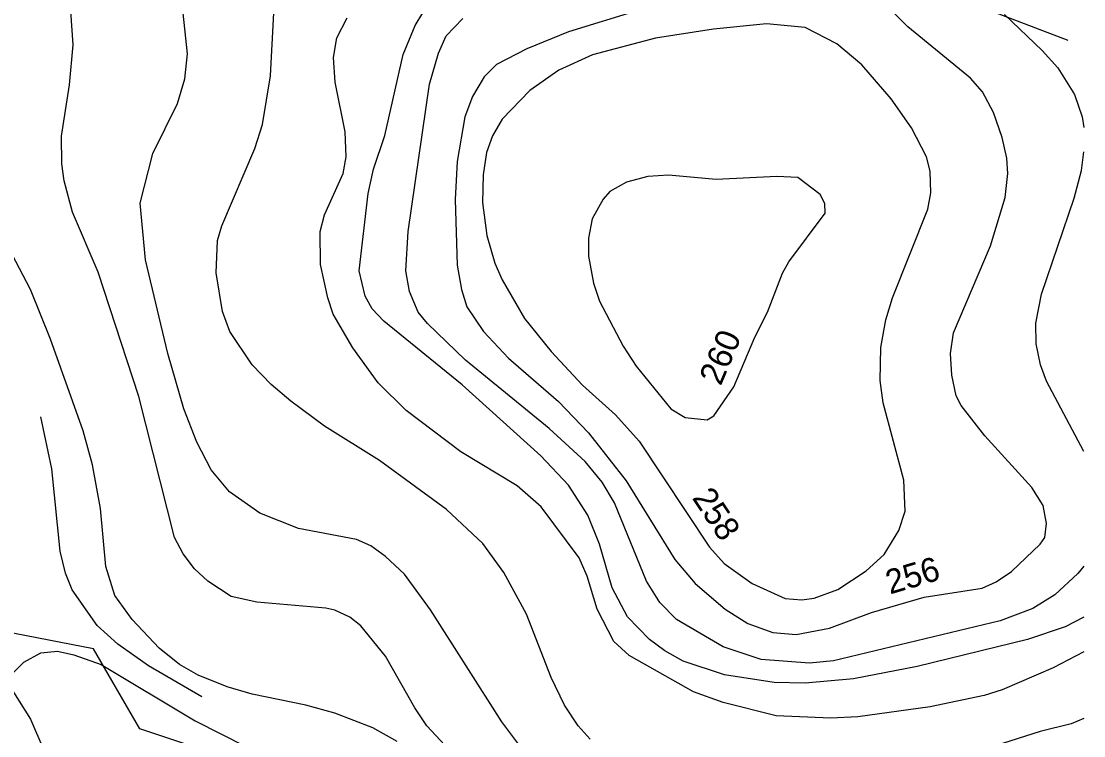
# Model space of a CAD drawing. Extents: x -662500 to -655523, y -1056000 to -1049993.
# Drawn here: x -659235.8 to -658797.7, y -1052866.9 to -1052572.3 of the extents above; entities that cross this region are included whole.
import ezdxf

# ---------------------------------------------------------------- set-up
doc = ezdxf.new("R2010")
doc.units = 0
doc.layers.add('Vrstva 24', color=7, linetype='Continuous')
doc.layers.add('Vrstva 7', color=7, linetype='Continuous')

msp = doc.modelspace()

# ---------------------------------------------------------------- linework, layer by layer
at = {"layer": 'Vrstva 24'}
for points in [[(-658804.21, -1052580.31), (-658897.5, -1052544.5), (-658920, -1052554.5), (-658965.5, -1052545)], [(-659139, -1052880), (-659187, -1052864), (-659206, -1052831), (-659248, -1052823), (-659254.5, -1052824.5), (-659232, -1052860), (-659216, -1052897.5)]]:
    msp.add_lwpolyline(points, dxfattribs=at)
at = {"layer": 'Vrstva 7'}
for p, q in [((-659167.29, -1052585.76), (-659170.28, -1052557.57)), ((-658870.28, -1052574.66), (-658888.08, -1052556.72)), ((-659214.41, -1052582.06), (-659215.41, -1052568.11)), ((-658980.62, -1052567.54), (-659010.24, -1052576.65)), ((-659133.11, -1052594.88), (-659131.69, -1052568.82)), ((-659105.78, -1052579.21), (-659101.51, -1052570.96)), ((-659073.46, -1052574.09), (-659070.32, -1052568.82)), ((-659060.64, -1052578.36), (-659053.81, -1052571.24)), ((-658830.41, -1052569.53), (-658814.89, -1052584.34)), ((-659078.3, -1052586.05), (-659073.46, -1052574.09)), ((-659010.24, -1052576.65), (-659027.33, -1052583.63)), ((-658950.44, -1052575.51), (-658974.36, -1052579.35)), ((-658928.51, -1052573.38), (-658950.44, -1052575.51)), ((-658912.57, -1052574.94), (-658928.51, -1052573.38)), ((-658899.61, -1052581.63), (-658912.57, -1052574.94)), ((-658844.37, -1052595.73), (-658870.28, -1052574.66)), ((-659107.06, -1052587.19), (-659105.78, -1052579.21)), ((-659063.77, -1052585.48), (-659060.64, -1052578.36)), ((-658974.36, -1052579.35), (-659000.27, -1052586.19)), ((-659215.98, -1052598.58), (-659214.41, -1052582.06)), ((-659168.42, -1052596.01), (-659167.29, -1052585.76)), ((-659067.48, -1052598.29), (-659063.77, -1052585.48)), ((-659027.33, -1052583.63), (-659039.85, -1052590.18)), ((-658889.21, -1052590.32), (-658899.61, -1052581.63)), ((-658814.89, -1052584.34), (-658808.49, -1052591.46)), ((-659106.35, -1052597.44), (-659107.06, -1052587.19)), ((-659085.98, -1052619.36), (-659078.3, -1052586.05)), ((-659039.85, -1052590.18), (-659044.98, -1052595.16)), ((-659000.27, -1052586.19), (-659014.23, -1052592.46)), ((-659014.23, -1052592.46), (-659026.19, -1052600.85)), ((-658877.11, -1052604.27), (-658889.21, -1052590.32)), ((-658808.49, -1052591.46), (-658801.51, -1052602.56)), ((-659219.25, -1052619.65), (-659215.98, -1052598.58)), ((-659171.41, -1052606.27), (-659168.42, -1052596.01)), ((-659136.39, -1052614.81), (-659133.11, -1052594.88)), ((-659102.22, -1052617.94), (-659106.35, -1052597.44)), ((-659076.3, -1052658.95), (-659067.48, -1052598.29)), ((-659044.98, -1052595.16), (-659049.82, -1052603.27)), ((-658839.53, -1052601.43), (-658844.37, -1052595.73)), ((-659049.82, -1052603.27), (-659052.95, -1052611.68)), ((-659026.19, -1052600.85), (-659037.58, -1052612.67)), ((-658834.97, -1052609.97), (-658839.53, -1052601.43)), ((-658801.51, -1052602.56), (-658798.38, -1052611.68)), ((-659181.52, -1052626.77), (-659171.41, -1052606.27)), ((-658868.71, -1052616.23), (-658877.11, -1052604.27)), ((-659052.95, -1052611.68), (-659056.08, -1052630.19)), ((-658831.41, -1052620.22), (-658834.97, -1052609.97)), ((-658798.38, -1052611.68), (-658797.74, -1052616.18)), ((-659139.52, -1052624.77), (-659136.39, -1052614.81)), ((-659037.58, -1052612.67), (-659041.56, -1052619.51)), ((-658862.59, -1052628.19), (-658868.71, -1052616.23)), ((-659219.11, -1052631.04), (-659219.25, -1052619.65)), ((-659101.93, -1052628.19), (-659102.22, -1052617.94)), ((-659090.54, -1052633.32), (-659085.98, -1052619.36)), ((-659041.56, -1052619.51), (-659043.98, -1052626.48)), ((-658829.42, -1052628.76), (-658831.41, -1052620.22)), ((-659153.19, -1052656.67), (-659139.52, -1052624.77)), ((-659186.79, -1052647.27), (-659181.52, -1052626.77)), ((-659103.07, -1052635.03), (-659101.93, -1052628.19)), ((-659043.98, -1052626.48), (-659045.41, -1052635.6)), ((-658861.02, -1052634.17), (-658862.59, -1052628.19)), ((-658828.99, -1052635.03), (-658829.42, -1052628.76)), ((-658798.66, -1052633.89), (-658797.74, -1052626.2)), ((-659218.11, -1052638.16), (-659219.11, -1052631.04)), ((-659092.82, -1052643.28), (-659090.54, -1052633.32)), ((-659056.08, -1052630.19), (-659056.94, -1052645.85)), ((-658801.65, -1052645.28), (-658798.66, -1052633.89)), ((-659232.07, -1052682.87), (-659257.27, -1052635.03)), ((-659214.7, -1052650.97), (-659218.11, -1052638.16)), ((-659110.76, -1052652.11), (-659103.07, -1052635.03)), ((-659045.41, -1052635.6), (-659045.69, -1052646.99)), ((-658977.49, -1052636.31), (-658986.29, -1052638.72)), ((-658968.95, -1052635.74), (-658977.49, -1052636.31)), ((-658949.3, -1052637.59), (-658968.95, -1052635.74)), ((-658924.24, -1052636.31), (-658949.3, -1052637.59)), ((-658915.7, -1052636.74), (-658924.24, -1052636.31)), ((-658906.49, -1052643.74), (-658915.7, -1052636.74)), ((-658860.74, -1052643), (-658861.02, -1052634.17)), ((-658830.13, -1052644.99), (-658828.99, -1052635.03)), ((-658993.09, -1052642.52), (-658995.93, -1052645.6)), ((-658986.29, -1052638.72), (-658993.09, -1052642.52)), ((-659096.52, -1052675.18), (-659092.82, -1052643.28)), ((-659056.94, -1052645.85), (-659056.08, -1052672.9)), ((-659045.69, -1052646.99), (-659043.84, -1052660.66)), ((-658995.93, -1052645.6), (-659000.42, -1052653.82)), ((-658904.44, -1052647.38), (-658906.49, -1052643.74)), ((-658862.02, -1052649.83), (-658860.74, -1052643)), ((-658836.25, -1052664.93), (-658830.13, -1052644.99)), ((-658815.18, -1052684.86), (-658801.65, -1052645.28)), ((-659204.16, -1052675.75), (-659214.7, -1052650.97)), ((-659184.66, -1052670.62), (-659186.79, -1052647.27)), ((-658919.4, -1052671.48), (-658904.36, -1052651.49)), ((-658904.36, -1052651.49), (-658904.44, -1052647.38)), ((-658876.54, -1052686.28), (-658862.02, -1052649.83)), ((-659112.61, -1052658.95), (-659110.76, -1052652.11)), ((-659000.42, -1052653.82), (-659001.98, -1052661.79)), ((-659154.9, -1052662.65), (-659153.19, -1052656.67)), ((-659112.47, -1052672.61), (-659112.61, -1052658.95)), ((-659077.3, -1052675.18), (-659076.3, -1052658.95)), ((-659155.47, -1052676.03), (-659154.9, -1052662.65)), ((-659043.84, -1052660.66), (-659040.57, -1052672.05)), ((-659001.98, -1052661.79), (-659001.98, -1052669.2)), ((-658851.48, -1052700.81), (-658836.25, -1052664.93)), ((-659175.4, -1052709.35), (-659184.66, -1052670.62)), ((-659109.48, -1052686.28), (-659112.47, -1052672.61)), ((-659056.08, -1052672.9), (-659054.38, -1052682.87)), ((-659040.57, -1052672.05), (-659037.58, -1052678.88)), ((-659001.98, -1052669.2), (-658999.84, -1052680.3)), ((-658921.96, -1052676.17), (-658919.4, -1052671.48)), ((-659187.36, -1052727), (-659204.16, -1052675.75)), ((-659152.9, -1052691.98), (-659155.47, -1052676.03)), ((-659094.1, -1052685.71), (-659096.52, -1052675.18)), ((-659075.73, -1052683.72), (-659077.3, -1052675.18)), ((-658928.08, -1052692.26), (-658921.96, -1052676.17)), ((-659037.58, -1052678.88), (-659028.32, -1052694.83)), ((-658999.84, -1052680.3), (-658997.43, -1052687.71)), ((-659223.81, -1052703.37), (-659232.07, -1052682.87)), ((-659107.2, -1052693.12), (-659109.48, -1052686.28)), ((-659091.11, -1052690.84), (-659094.1, -1052685.71)), ((-659072.18, -1052692.26), (-659075.73, -1052683.72)), ((-659054.38, -1052682.87), (-659052.1, -1052689.99)), ((-658879.39, -1052695.4), (-658876.54, -1052686.28)), ((-658817.45, -1052696.82), (-658815.18, -1052684.86)), ((-659086.27, -1052695.97), (-659091.11, -1052690.84)), ((-659052.1, -1052689.99), (-659045.26, -1052700.24)), ((-658997.43, -1052687.71), (-658987.6, -1052706.22)), ((-659149.77, -1052700.24), (-659152.9, -1052691.98)), ((-659099.08, -1052706.93), (-659107.2, -1052693.12)), ((-659068.33, -1052696.96), (-659072.18, -1052692.26)), ((-659028.32, -1052694.83), (-659017.36, -1052708.5)), ((-658933.35, -1052702.52), (-658928.08, -1052692.26)), ((-659054.09, -1052722.16), (-659086.27, -1052695.97)), ((-659052.67, -1052712.05), (-659068.33, -1052696.96)), ((-658881.38, -1052706.79), (-658879.39, -1052695.4)), ((-658817.31, -1052705.36), (-658817.45, -1052696.82)), ((-659210.28, -1052741.24), (-659223.81, -1052703.37)), ((-659140.66, -1052713.91), (-659149.77, -1052700.24)), ((-659045.26, -1052700.24), (-659034.87, -1052711.2)), ((-658942.04, -1052723.02), (-658933.35, -1052702.52)), ((-658852.62, -1052709.35), (-658851.48, -1052700.81)), ((-659088.69, -1052721.45), (-659099.08, -1052706.93)), ((-659017.36, -1052708.5), (-659004.4, -1052722.31)), ((-658987.6, -1052706.22), (-658982.33, -1052714.48)), ((-658881.67, -1052720.46), (-658881.38, -1052706.79)), ((-658815.6, -1052713.91), (-658817.31, -1052705.36)), ((-659168.85, -1052732.13), (-659175.4, -1052709.35)), ((-659018.21, -1052740.25), (-659052.67, -1052712.05)), ((-659034.87, -1052711.2), (-659014.37, -1052729.14)), ((-658852.2, -1052718.18), (-658852.62, -1052709.35)), ((-659132.83, -1052722.02), (-659140.66, -1052713.91)), ((-658982.33, -1052714.48), (-658967.95, -1052732.13)), ((-658813.04, -1052720.74), (-658815.6, -1052713.91)), ((-659077.16, -1052732.84), (-659088.69, -1052721.45)), ((-658880.39, -1052729.57), (-658881.67, -1052720.46)), ((-658850.34, -1052726.72), (-658852.2, -1052718.18)), ((-658797.74, -1052749.73), (-658813.04, -1052720.74)), ((-659124.71, -1052729), (-659132.83, -1052722.02)), ((-659021.63, -1052751.49), (-659054.09, -1052722.16)), ((-659004.4, -1052722.31), (-658990.88, -1052734.55)), ((-658950.29, -1052734.97), (-658942.04, -1052723.02)), ((-659172.7, -1052785.1), (-659187.36, -1052727)), ((-659110.76, -1052739.25), (-659124.71, -1052729)), ((-659014.37, -1052729.14), (-659001.98, -1052741.95)), ((-658871.99, -1052761.46), (-658880.39, -1052729.57)), ((-658848.35, -1052730.71), (-658850.34, -1052726.72)), ((-659163.44, -1052745.8), (-659168.85, -1052732.13)), ((-659054.52, -1052749.78), (-659077.16, -1052732.84)), ((-658990.88, -1052734.55), (-658981.05, -1052745.37)), ((-658967.95, -1052732.13), (-658962.11, -1052735.69)), ((-658838.53, -1052743.24), (-658848.35, -1052730.71)), ((-659223.24, -1052756.9), (-659227.8, -1052735.41)), ((-658962.11, -1052735.69), (-658952.97, -1052736.71)), ((-658952.97, -1052736.71), (-658950.29, -1052734.97)), ((-659206.44, -1052755.2), (-659210.28, -1052741.24)), ((-659088.12, -1052753.34), (-659110.76, -1052739.25)), ((-659003.26, -1052753.77), (-659018.21, -1052740.25)), ((-659001.98, -1052741.95), (-658986.46, -1052761.75)), ((-658819.16, -1052764.59), (-658838.53, -1052743.24)), ((-659157.6, -1052757.19), (-659163.44, -1052745.8)), ((-658981.05, -1052745.37), (-658952.01, -1052789.08)), ((-659031.31, -1052763.88), (-659054.52, -1052749.78)), ((-659010.24, -1052763.6), (-659021.63, -1052751.49)), ((-659203.17, -1052773.14), (-659206.44, -1052755.2)), ((-659060.5, -1052773.56), (-659088.12, -1052753.34)), ((-658996.29, -1052762.31), (-659003.26, -1052753.77)), ((-659219.82, -1052790.79), (-659223.24, -1052756.9)), ((-659149.92, -1052766.3), (-659157.6, -1052757.19)), ((-659021.49, -1052772.57), (-659031.31, -1052763.88)), ((-659002.27, -1052775.98), (-659010.24, -1052763.6)), ((-658991.16, -1052770.86), (-658996.29, -1052762.31)), ((-658986.46, -1052761.75), (-658966.39, -1052794.21)), ((-658871.42, -1052774.27), (-658871.99, -1052761.46)), ((-658814.47, -1052772), (-658819.16, -1052764.59)), ((-659137.53, -1052775.13), (-659149.92, -1052766.3)), ((-659201.03, -1052797.06), (-659203.17, -1052773.14)), ((-659045.55, -1052787.66), (-659060.5, -1052773.56)), ((-659005.83, -1052793.5), (-659021.49, -1052772.57)), ((-658978.06, -1052803.18), (-658991.16, -1052770.86)), ((-658813.04, -1052779.4), (-658814.47, -1052772)), ((-659121.58, -1052781.39), (-659137.53, -1052775.13)), ((-658997.42, -1052787.94), (-659002.27, -1052775.98)), ((-658873.98, -1052782.25), (-658871.42, -1052774.27)), ((-659097.66, -1052785.95), (-659121.58, -1052781.39)), ((-658880.1, -1052792.22), (-658873.98, -1052782.25)), ((-658813.75, -1052785.1), (-658813.04, -1052779.4)), ((-659169.14, -1052791.93), (-659172.7, -1052785.1)), ((-659091.68, -1052788.66), (-659097.66, -1052785.95)), ((-658815.75, -1052787.94), (-658813.75, -1052785.1)), ((-659217.55, -1052799.9), (-659219.82, -1052790.79)), ((-659085.7, -1052792.93), (-659091.68, -1052788.66)), ((-659036.86, -1052799.62), (-659045.55, -1052787.66)), ((-658992.16, -1052805.88), (-658997.42, -1052787.94)), ((-658952.01, -1052789.08), (-658946.03, -1052795.92)), ((-658827.56, -1052799.19), (-658815.75, -1052787.94)), ((-659164.44, -1052798.05), (-659169.14, -1052791.93)), ((-659077.87, -1052800.33), (-659085.7, -1052792.93)), ((-659002.55, -1052801.04), (-659005.83, -1052793.5)), ((-658966.39, -1052794.21), (-658957.98, -1052804.18)), ((-658946.03, -1052795.92), (-658934.49, -1052804.17)), ((-658887.51, -1052798.91), (-658880.1, -1052792.22)), ((-659214.84, -1052806.74), (-659217.55, -1052799.9)), ((-659197.19, -1052809.02), (-659201.03, -1052797.06)), ((-659158.89, -1052803.18), (-659164.44, -1052798.05)), ((-659067.05, -1052815), (-659077.87, -1052800.33)), ((-659027.47, -1052816.7), (-659036.86, -1052799.62)), ((-658899.18, -1052806.59), (-658887.51, -1052798.91)), ((-658833.83, -1052803.46), (-658827.56, -1052799.19)), ((-658800.23, -1052800.05), (-658809.62, -1052808.73)), ((-658797.74, -1052796.94), (-658800.23, -1052800.05)), ((-659149.34, -1052809.44), (-659158.89, -1052803.18)), ((-658998.42, -1052814.71), (-659002.55, -1052801.04)), ((-658972.51, -1052812.01), (-658978.06, -1052803.18)), ((-658957.98, -1052804.18), (-658945.6, -1052814.71)), ((-658934.49, -1052804.17), (-658920.82, -1052810.3)), ((-658839.67, -1052806.03), (-658833.83, -1052803.46)), ((-659204.59, -1052821.4), (-659214.84, -1052806.74)), ((-659190.07, -1052818.98), (-659197.19, -1052809.02)), ((-658985.89, -1052817.84), (-658992.16, -1052805.88)), ((-658908.86, -1052810.15), (-658899.18, -1052806.59)), ((-658863.59, -1052809.73), (-658839.67, -1052806.03)), ((-658809.62, -1052808.73), (-658818.74, -1052814.43)), ((-659138.67, -1052811.86), (-659149.34, -1052809.44)), ((-659110.19, -1052814.28), (-659138.67, -1052811.86)), ((-658965.67, -1052818.98), (-658972.51, -1052812.01)), ((-658920.82, -1052810.3), (-658913.99, -1052810.87)), ((-658913.99, -1052810.87), (-658908.86, -1052810.15)), ((-658885.23, -1052816.13), (-658863.59, -1052809.73)), ((-659106.49, -1052815.14), (-659110.19, -1052814.28)), ((-659100.37, -1052817.99), (-659106.49, -1052815.14)), ((-659095.81, -1052821.54), (-659100.37, -1052817.99)), ((-659037.72, -1052861.13), (-659067.05, -1052815)), ((-659017.36, -1052842.9), (-659027.47, -1052816.7)), ((-658991.45, -1052828.09), (-658998.42, -1052814.71)), ((-658976.78, -1052827.24), (-658985.89, -1052817.84)), ((-658945.6, -1052814.71), (-658936.2, -1052820.55)), ((-658902.6, -1052822.54), (-658885.23, -1052816.13)), ((-658818.74, -1052814.43), (-658832.26, -1052819.55)), ((-658797.74, -1052817.96), (-658805.35, -1052821.97)), ((-659196.05, -1052829.09), (-659204.59, -1052821.4)), ((-659178.96, -1052830.8), (-659190.07, -1052818.98)), ((-659085.7, -1052834.07), (-659095.81, -1052821.54)), ((-658946.45, -1052830.23), (-658965.67, -1052818.98)), ((-658936.2, -1052820.55), (-658925.95, -1052824.39)), ((-658832.26, -1052819.55), (-658900.89, -1052836.07)), ((-658805.35, -1052821.97), (-658820.87, -1052827.24)), ((-658925.95, -1052824.39), (-658916.27, -1052825.1)), ((-658916.27, -1052825.1), (-658902.6, -1052822.54)), ((-659183.37, -1052838.06), (-659196.05, -1052829.09)), ((-659170.56, -1052837.49), (-659178.96, -1052830.8)), ((-658985.18, -1052833.79), (-658991.45, -1052828.09)), ((-658970.52, -1052831.94), (-658976.78, -1052827.24)), ((-658930.79, -1052835.5), (-658946.45, -1052830.23)), ((-658820.87, -1052827.24), (-658866.44, -1052838.35)), ((-659234.77, -1052836.5), (-659227.8, -1052832.65)), ((-659227.8, -1052832.65), (-659220.96, -1052832.08)), ((-659220.96, -1052832.08), (-659214.13, -1052833.51)), ((-659214.13, -1052833.51), (-659202.88, -1052837.49)), ((-659073.6, -1052855.43), (-659085.7, -1052834.07)), ((-658958.7, -1052848.74), (-658985.18, -1052833.79)), ((-658962.97, -1052836.21), (-658970.52, -1052831.94)), ((-658910.86, -1052836.92), (-658930.79, -1052835.5)), ((-658797.74, -1052832.26), (-658810.34, -1052838.92)), ((-659239.76, -1052841.48), (-659234.77, -1052836.5)), ((-659202.88, -1052837.49), (-659164.15, -1052860.7)), ((-659161.33, -1052850.91), (-659183.37, -1052838.06)), ((-659162.87, -1052841.91), (-659170.56, -1052837.49)), ((-658945.88, -1052841.76), (-658962.97, -1052836.21)), ((-658900.89, -1052836.07), (-658910.86, -1052836.92)), ((-658866.44, -1052838.35), (-658892.63, -1052843.47)), ((-658810.34, -1052838.92), (-658831.41, -1052848.03)), ((-659150.91, -1052846.75), (-659162.87, -1052841.91)), ((-659011.81, -1052854.29), (-659017.36, -1052842.9)), ((-658925.38, -1052844.9), (-658945.88, -1052841.76)), ((-658892.63, -1052843.47), (-658912.57, -1052845.18)), ((-659140.66, -1052849.74), (-659150.91, -1052846.75)), ((-658912.57, -1052845.18), (-658925.38, -1052844.9)), ((-658831.41, -1052848.03), (-658838.81, -1052850.31)), ((-659118.45, -1052854.29), (-659140.66, -1052849.74)), ((-658946.45, -1052853.15), (-658958.7, -1052848.74)), ((-658838.81, -1052850.31), (-658861.02, -1052855)), ((-659106.49, -1052857.57), (-659118.45, -1052854.29)), ((-659068.61, -1052862.84), (-659073.6, -1052855.43)), ((-659006.25, -1052862.84), (-659011.81, -1052854.29)), ((-658924.53, -1052858.71), (-658946.45, -1052853.15)), ((-658861.02, -1052855), (-658890.92, -1052859.13)), ((-659164.15, -1052860.7), (-659143.22, -1052871.38)), ((-659090.83, -1052863.69), (-659106.49, -1052857.57)), ((-659026.19, -1052876.5), (-659037.72, -1052861.13)), ((-658902.03, -1052859.7), (-658924.53, -1052858.71)), ((-658890.92, -1052859.13), (-658902.03, -1052859.7)), ((-658797.74, -1052859.8), (-658802.93, -1052861.98)), ((-659080.86, -1052869.24), (-659090.83, -1052863.69)), ((-659045.27, -1052887.61), (-659068.61, -1052862.84)), ((-659001.27, -1052868.25), (-659006.25, -1052862.84)), ((-658815.75, -1052865.11), (-658834.26, -1052871.09)), ((-658802.93, -1052861.98), (-658815.75, -1052865.11))]:
    msp.add_line(p, q, dxfattribs=at)

# ---------------------------------------------------------------- texts
for s, rotation, p in [('260', 67.0403, (-658947.44, -1052722.96)), ('258', 303.6035, (-658959.47, -1052768.82)), ('256', 16.4887, (-658877.67, -1052808.68))]:
    msp.add_text(s, height=10, rotation=rotation, dxfattribs=at).set_placement(p)

doc.saveas('drawing.dxf')
